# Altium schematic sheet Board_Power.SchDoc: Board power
size A4; Date: Not used; ApprovedBy: Not used; CheckedBy: Not used; Author: Not used; CompanyName: STMicroelectronics; DrawnBy: Not used; Engineer: Not used; Organization: Not used; Address1: Not used; Address2: Not used; Address3: Not used; Address4: Not used; DocumentNumber: 5; Revision: Not used; SheetNumber: 5; SheetTotal: 8
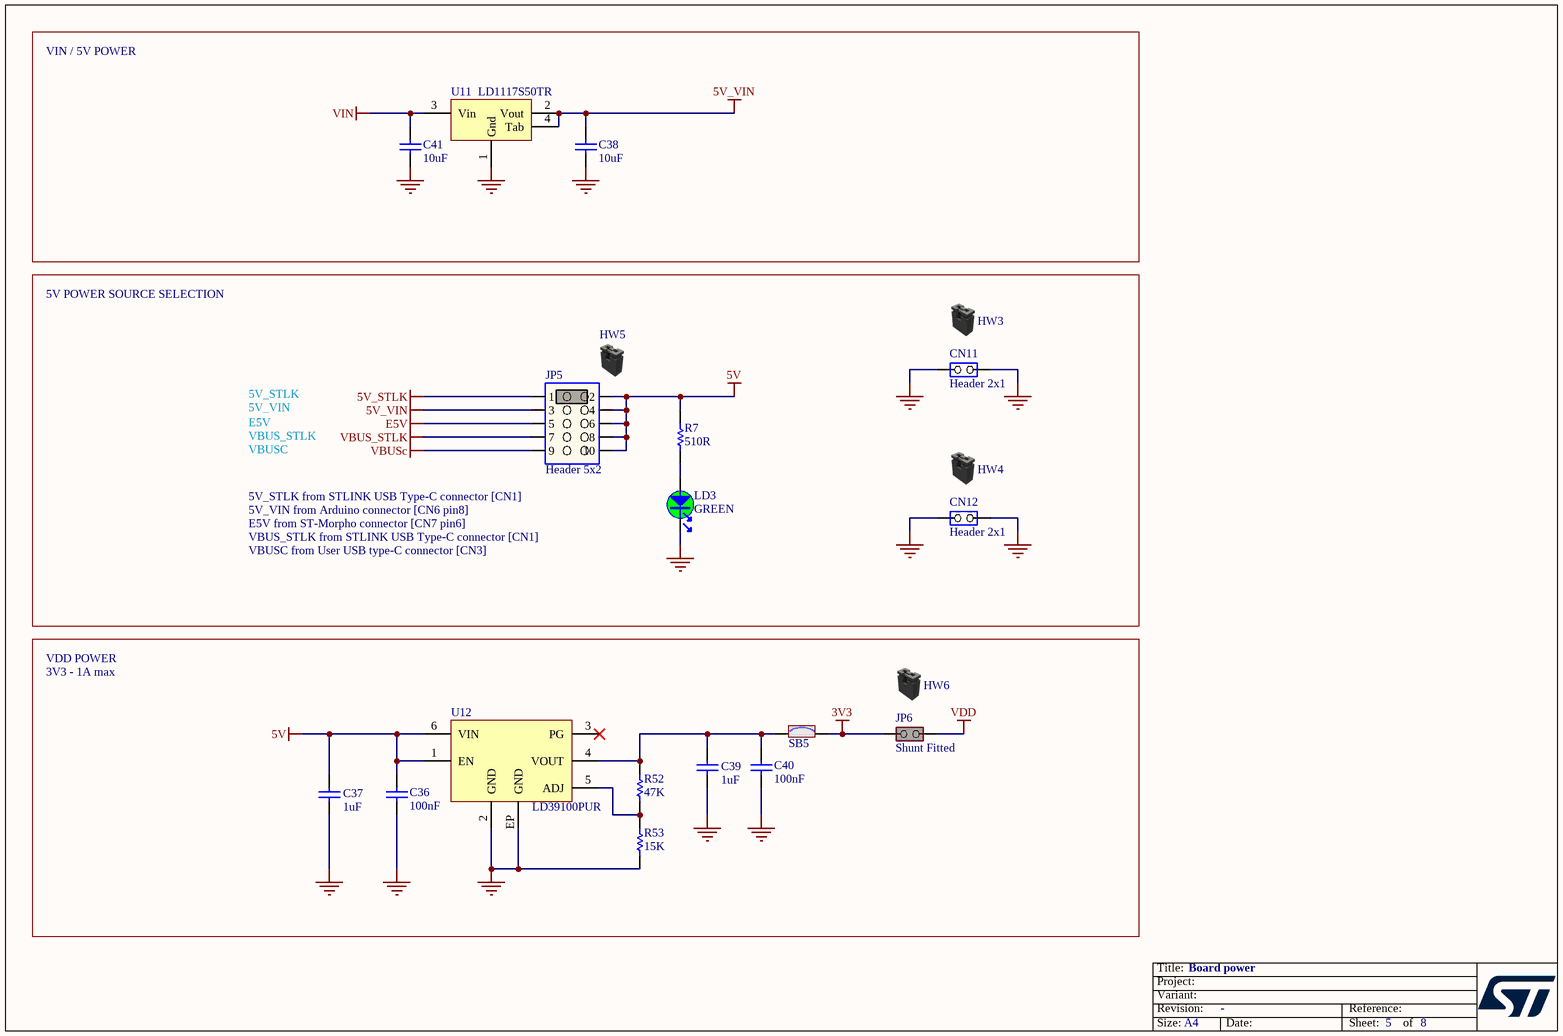
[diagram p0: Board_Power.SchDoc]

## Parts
C36  value 100nF  [C0402]  (hidden comment: Capacitor)
C37  value 1uF  [C0603]
C38  value 10uF  [C0805]
C39  value 1uF  [C0603]
C40  value 100nF  [C0402]  (hidden comment: Capacitor)
C41  value 10uF  [C0805]
CN11  value Header 2x1  [CON_SAMTEC_TSW-102-09-X-S]  (hidden comment: Jumper_Header 2x1)
CN12  value Header 2x1  [CON_SAMTEC_TSW-102-09-X-S]  (hidden comment: Jumper_Header 2x1)
HW3  (no value)  (mechanical)
HW4  (no value)  (mechanical)
HW5  (no value)  (mechanical)
HW6  (no value)  (mechanical)
JP5  value Header 5x2  [CON_SAMTEC_TSW-105-07-X-D]  (hidden comment: Jumper_Header 5x2 Fitted 1-2)
JP6  Shunt Fitted  [CON_SAMTEC_TSW-102-07-G-S]
LD3  value GREEN  [LED_0603_OSRAM_LG-Q396-PS-35_GREEN_1A2K_H0P4]  (hidden comment: LED_green)
R7  value 510R  [R0603]
R52  value 47K  [R0402]  (hidden comment: Resistor)
R53  value 15K  [R0402]  (hidden comment: Resistor)
SB5  (no value)  [SOLDER-BRIDGE_R0603-0R]
U11  value LD1117S50TR  [REG_SOT223-TAB]
U12  LD39100PUR  [ICC_DFN6-EPAD_3X3_P095]

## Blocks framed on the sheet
VIN / 5V POWER: C38 C41 U11

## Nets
3V3: JP6.1(COMMON) SB5.2
5V: C36.2 C37.2 JP5.2 JP5.4 JP5.6 JP5.8 JP5.10 R7.2 U12.1(EN) U12.6(VIN)
5V_STLK: JP5.1
5V_VIN: C38.2 JP5.3 U11.2(Vout) U11.4(Tab)
E5V: JP5.5
GND: C36.1 C37.1 C38.1 C39.1 C40.1 C41.1 CN11.1(COMMON) CN11.2(NO) CN12.1(COMMON) CN12.2(NO) LD3.2 R53.1 U11.1(Gnd) U12.2(GND) U12.EP(GND)
VBUS_STLK: JP5.7
VBUSc: JP5.9
VDD: JP6.2(NO)
VIN: C41.2 U11.3(Vin)
NetC39_2: C39.2 C40.2 R52.2 SB5.1 U12.4(VOUT)
NetLD3_1: LD3.1 R7.1
NetR52_1: R52.1 R53.2 U12.5(ADJ)

Not connected (* = marked no-connect by the designer): U12 3(PG)*

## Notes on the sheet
- 5V POWER SOURCE SELECTION
- 5V_STLK
- E5V
- 5V_VIN
- VBUS_STLK
- VBUSC
- 5V_VIN from Arduino connector [CN6 pin8]
- (near JP5) 5V_STLK from STLINK USB Type-C connector [CN1]
- E5V from ST-Morpho connector [CN7 pin6]
- VBUS_STLK from STLINK USB Type-C connector [CN1]
- VBUSC from User USB type-C connector [CN3]
- VDD POWER
- 3V3 - 1A max

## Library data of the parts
C36 C40 = MCD-00006: Capacitor, MLCC, 100nF, 16V, X7R, +/-10%, 0402, T=0.5mm; Part_Preference: Recommended; Manufacturer: YAGEO; Manufacturer_Part_Number: CC0402KRX7R7BB104; Partial_Alternate_Internal_Part_Number: MCD-03299; Order_Code_RS: 9402047; Component_Country_Of_Origin: China; ShowFields: YES; ID: 2474
C37 C39 = MCD-00010: Capacitor, MLCC, 1uF, 16V, X5R, 10%, 0603, T=0,8mm; Manufacturer_Part_Number: CC0603KRX5R7BB105; Manufacturer: YAGEO; Provided_By: Subcon; Initial_Board_Reference: MB1274
C38 C41 = MCD-00014: Capacitor, MLCC, 10uF, 25V, X5R, 10%, 0805, T=0,85mm; Manufacturer_Part_Number: CC0805KRX5R8BB106; Manufacturer: YAGEO; ECCN_US: EAR99; ECCN_EU: NEC; Provided_By: SUBCO
CN11 CN12 = MCD-00214: Header, 2x1, 2.54mm, VR, TH, T=5.84mm/10.16mm; Part_Type: Connector; Part_Preference: Recommended; Manufacturer: SAMTEC; Manufacturer_Part_Number: TSW-102-09-G-S; Alternate_Internal_Part_Number: MCD-02393; Order_Code_RS: 180-3129; Component_Country_Of_Origin: China, Costa Rica, Malaysia, United States, Vietnam; ShowFields: YES; ID: 2652
HW3-HW6 = MCD-00043: SHUNT 2.54mm BLACK; Manufacturer_Part_Number: SNT-100-BK-G; Manufacturer: SAMTEC; Part_Type: Mechanical; Provided_By: Subcon; Initial_Board_Reference: MB1274
JP5 = MCD-01203: Header, 5x2, 2.54mm, VR, TH, T=5.84mm/2.54mm; BMS_Part_Number: 9083523; Part_Type: Connector; Part_Preference: Recommended; Manufacturer: SAMTEC; Manufacturer_Part_Number: TSW-105-07-G-D; Alternate_Internal_Part_Number: MCD-02391; Order_Code_RS: 161-2267; Component_Country_Of_Origin: China, Costa Rica, Malaysia, United States, Vietnam; ShowFields: YES; ID: 3293
JP6 = MCD-00683: Header, 2x1, 2,54mm, VR, TH, Height 5.84mm/2.54mm - Shunt Fitted by default; Part_Type: Connector; Manufacturer_Part_Number: TSW-102-07-x-S; Manufacturer: SAMTEC; Provided_By: Subcon; Initial_Board_Reference: MB1331
LD3 = MCD-00588: LED Green, 0603 SMD, Forward Voltage Typ=2V, Max=2.5V; Part_Type: Display; Manufacturer_Part_Number: LG Q396-PS-35; Manufacturer: OSRAM OPTO SEMICONDUCTORS; Alternate_Manufacturer_Part_Number: VLMTG1300-GS08; Alternate_Manufacturer: VISHAY SEMICONDUCTOR OPTO DIVISION; Provided_By: SUBCO
R7 = MCD-00225: Resistor,510R,0603,1%,1/10W; Manufacturer_Part_Number: RC0603FR-07510RL; Manufacturer: YAGEO; ECCN_US: EAR99; ECCN_EU: NEC; Provided_By: SUBCO
R52 = MCD-00063: Resistor, 47K, 0402, +/-1%, 1/16W; Part_Preference: Recommended; Manufacturer: YAGEO; Manufacturer_Part_Number: RC0402FR-0747KL; Component_Country_Of_Origin: China; ShowFields: YES; ID: 2528
R53 = MCD-01943: Resistor, 15K, 0402, +/-1%, 1/16W; Part_Preference: Recommended; Manufacturer: YAGEO; Manufacturer_Part_Number: RC0402FR-0715KL; Order_Code_RS: 618-6009; Component_Country_Of_Origin: China; ShowFields: YES; ID: 4043
SB5 = MCD-00071: Solder Bridge ON; Part_Type: Mechanical; Manufacturer_Part_Number: RC0603JR-070RL; Manufacturer: YAGEO; Provided_By: SUBCO
U11 = MCD-00088: IC REG LDO 5V 0.8A SOT223; Manufacturer: STMICROELECTRONICS; BMS_Part_Number: 9176133; ECCN_US: EAR99; ECCN_EU: NEC; Provided_By: SUBCO with ST control
U12 = MCD-03339: LDO, 1V5 to 5V5V, 1A adjustable; Part_Type: IC; Part_Preference: Recommended; Manufacturer: STMICROELECTRONICS; Component_Country_Of_Origin: Malaysia; ShowFields: YES; ID: 5455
